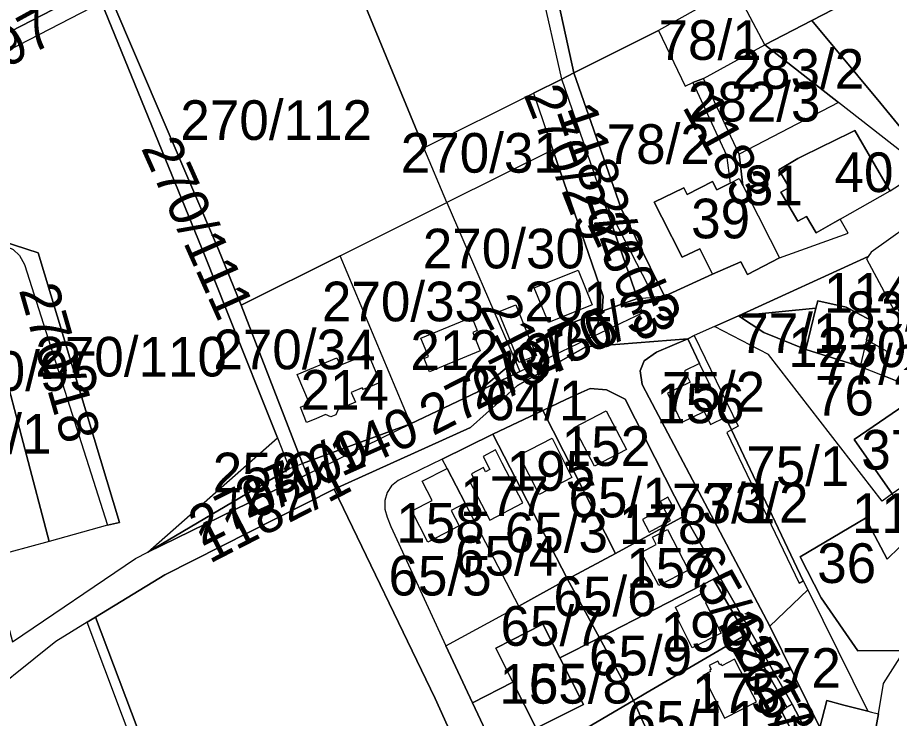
# Model space of a CAD drawing. Extents: x -623250 to -619626, y -1079612 to -1075424.
# Drawn here: x -621589.3 to -621368.8, y -1077090.4 to -1076913.6 of the extents above; entities that cross this region are included whole.
import ezdxf

# ---------------------------------------------------------------- set-up
doc = ezdxf.new("R2010")
doc.units = 0
doc.layers.add('Parcela nároku', color=7, linetype='Continuous')
doc.layers.add('Parcelní číslo', color=7, linetype='Continuous')

msp = doc.modelspace()

# ---------------------------------------------------------------- linework, layer by layer
at = {"layer": 'Parcela nároku'}
for points in [[(-621497.66, -1076887.41), (-621510.34, -1076889.38), (-621486.81, -1076946.46), (-621459.16, -1076932.7), (-621452.03, -1076929.15), (-621457.25, -1076905.73), (-621474.71, -1076864.09), (-621476.89, -1076864.41), (-621478.08, -1076856.31), (-621500.78, -1076808.08), (-621508.66, -1076809.23), (-621510.33, -1076797.86), (-621505.84, -1076797.19), (-621517.12, -1076774.19), (-621510.8, -1076809.47), (-621510.52, -1076812.14), (-621506.39, -1076828.53)], [(-621642.51, -1076849.57), (-621599.1, -1076820.91), (-621569.66, -1076906.06), (-621617.71, -1076930.85), (-621620.46, -1076931.89), (-621623.96, -1076932.1), (-621628.28, -1076930.73), (-621636.53, -1076902.24), (-621642.52, -1076868.77), (-621642.24, -1076853.29), (-621640.35, -1076852.51)], [(-621265.61, -1076833.49), (-621261.7, -1076848.72), (-621388.91, -1076914.43), (-621400.8, -1076920.49), (-621408.16, -1076906.52), (-621369.25, -1076886.43), (-621369.11, -1076886.7)], [(-621388.91, -1076914.43), (-621261.7, -1076848.72), (-621265.74, -1076862.26), (-621268.27, -1076865.58), (-621302.1, -1076905.64), (-621306.34, -1076911.31), (-621320.09, -1076923.81), (-621321.03, -1076924.46), (-621358.9, -1076950.67), (-621371.51, -1076935.3)], [(-621469.68, -1076868.53), (-621462.22, -1076885.24), (-621454.35, -1076902.86), (-621448.96, -1076927.61), (-621452.03, -1076929.15), (-621457.25, -1076905.73), (-621474.71, -1076864.09), (-621471.85, -1076863.67)], [(-621542.97, -1076896.85), (-621565.72, -1076908.58), (-621538.54, -1076972.15), (-621532.87, -1076986.13), (-621507.89, -1076973.7), (-621480.99, -1076960.31), (-621486.81, -1076946.46), (-621510.34, -1076889.38), (-621532.05, -1076893.05), (-621536.11, -1076893.99)], [(-621628.28, -1076930.73), (-621623.96, -1076932.1), (-621620.46, -1076931.89), (-621617.71, -1076930.85), (-621569.66, -1076906.06), (-621568.12, -1076909.82), (-621615.27, -1076934.15), (-621617.53, -1076935.48), (-621622.22, -1076939.58), (-621624.82, -1076942.64)], [(-621400.8, -1076920.49), (-621408.16, -1076906.52), (-621418.09, -1076911.65), (-621427.65, -1076916.93), (-621420.86, -1076930.98), (-621418.93, -1076930.03), (-621416.28, -1076928.99)], [(-621615.27, -1076934.15), (-621617.53, -1076935.48), (-621622.22, -1076939.58), (-621624.82, -1076942.64), (-621620.2, -1076960.77), (-621598.92, -1076968.16), (-621584.09, -1076972.99), (-621563.58, -1077040.98), (-621566.61, -1077041.67), (-621581.27, -1077045.75), (-621596.25, -1077049.81), (-621590.54, -1077071.06), (-621559.55, -1077050.01), (-621556.43, -1077048.44), (-621523.67, -1077019.62), (-621536.39, -1076987.8), (-621541.98, -1076973.85), (-621568.12, -1076909.82)], [(-621532.87, -1076986.13), (-621538.54, -1076972.15), (-621565.72, -1076908.58), (-621568.12, -1076909.82), (-621541.98, -1076973.85), (-621536.39, -1076987.8), (-621523.67, -1077019.62), (-621520.7, -1077027.31), (-621517.41, -1077026.07)], [(-621400.8, -1076920.49), (-621388.91, -1076914.43), (-621371.51, -1076935.3), (-621358.9, -1076950.67), (-621360.7, -1076951.91), (-621382.24, -1076935.03)], [(-621428.69, -1076960.22), (-621426.79, -1076963.96), (-621421.62, -1076974.1), (-621417.18, -1076971.93), (-621413.95, -1076978.36), (-621426.11, -1076983.89), (-621437.02, -1076961.76), (-621448.96, -1076927.61), (-621427.65, -1076916.93), (-621420.86, -1076930.98), (-621418.93, -1076930.03), (-621410.43, -1076948.36), (-621409.51, -1076955.38), (-621412.9, -1076957.1), (-621413.98, -1076954.99), (-621420.4, -1076958.27), (-621421.21, -1076956.59)], [(-621416.28, -1076928.99), (-621400.8, -1076920.49), (-621382.24, -1076935.03), (-621407.3, -1076948.06)], [(-621452.03, -1076929.15), (-621448.96, -1076927.61), (-621437.02, -1076961.76), (-621426.11, -1076983.89), (-621428.7, -1076984.16), (-621441.87, -1076958.52)], [(-621432.9, -1076984.48), (-621441.87, -1076958.52), (-621452.03, -1076929.15), (-621459.16, -1076932.7), (-621454.25, -1076947.01), (-621441.58, -1076983.87), (-621441.79, -1076987.68)], [(-621406.33, -1076956.01), (-621407.3, -1076948.06), (-621416.28, -1076928.99), (-621418.93, -1076930.03), (-621410.43, -1076948.36), (-621409.51, -1076955.38), (-621407.24, -1076954.23)], [(-621459.16, -1076932.7), (-621454.25, -1076947.01), (-621480.99, -1076960.31), (-621486.81, -1076946.46)], [(-621379.74, -1076967.98), (-621381.79, -1076964.51), (-621383.13, -1076965.27), (-621387.85, -1076967.95), (-621390.29, -1076963.84), (-621392.46, -1076965.01), (-621396.79, -1076957.69), (-621394.63, -1076956.52), (-621397.27, -1076952.05), (-621392.43, -1076949.18), (-621385.65, -1076945.85), (-621384.21, -1076945.15), (-621378.08, -1076942.14), (-621369.5, -1076956.9), (-621369.14, -1076957.33), (-621360.7, -1076951.91), (-621382.24, -1076935.03), (-621407.3, -1076948.06), (-621406.33, -1076956.01), (-621402.48, -1076963.6), (-621399.42, -1076969.63), (-621397.07, -1076974.26)], [(-621378.08, -1076942.14), (-621384.21, -1076945.15), (-621385.65, -1076945.85), (-621392.43, -1076949.18), (-621397.27, -1076952.05), (-621394.63, -1076956.52), (-621396.79, -1076957.69), (-621392.46, -1076965.01), (-621390.29, -1076963.84), (-621387.85, -1076967.95), (-621383.13, -1076965.27), (-621381.79, -1076964.51), (-621369.14, -1076957.33), (-621369.5, -1076956.9)], [(-621454.25, -1076947.01), (-621480.99, -1076960.31), (-621463.8, -1077000.14), (-621463.17, -1076999.62), (-621464.7, -1076995.86), (-621467.99, -1076987.82), (-621463.63, -1076986.06), (-621460.37, -1076994.09), (-621459.39, -1076996.45), (-621455.04, -1076992.81), (-621441.79, -1076987.68), (-621441.58, -1076983.87)], [(-621399.42, -1076969.63), (-621397.07, -1076974.26), (-621405.17, -1076978.41), (-621406.88, -1076975.24), (-621413.95, -1076978.36), (-621417.18, -1076971.93), (-621421.62, -1076974.1), (-621426.79, -1076963.96), (-621428.69, -1076960.22), (-621421.21, -1076956.59), (-621420.4, -1076958.27), (-621413.98, -1076954.99), (-621412.9, -1076957.1), (-621409.51, -1076955.38), (-621407.24, -1076954.23), (-621406.33, -1076956.01), (-621402.48, -1076963.6)], [(-621428.7, -1076984.16), (-621441.87, -1076958.52), (-621432.9, -1076984.48)], [(-621598.92, -1076968.16), (-621590.34, -1076972.12), (-621588.81, -1076973.64), (-621587.52, -1076975.91), (-621566.61, -1077041.67), (-621581.27, -1077045.75), (-621599.79, -1076975.67), (-621615.1, -1076979.74), (-621620.2, -1076960.77)], [(-621507.89, -1076973.7), (-621480.99, -1076960.31), (-621463.8, -1077000.14), (-621473.18, -1077007.98), (-621490.13, -1077016.07), (-621490.27, -1077015.75)], [(-621359.65, -1076964.2), (-621360.3, -1076963.02), (-621374.01, -1076972.77), (-621374.75, -1076973.9), (-621375.15, -1076974.51), (-621366.89, -1076989.84), (-621366.1, -1076989.42), (-621367.97, -1076985.39), (-621365.43, -1076983.95), (-621363.29, -1076987.92), (-621350.51, -1076980.67)], [(-621584.09, -1076972.99), (-621598.92, -1076968.16), (-621590.34, -1076972.12), (-621588.81, -1076973.64), (-621587.52, -1076975.91), (-621566.61, -1077041.67), (-621563.58, -1077040.98)], [(-621507.89, -1076973.7), (-621532.87, -1076986.13), (-621517.41, -1077026.07), (-621490.13, -1077016.07), (-621490.27, -1077015.75)], [(-621617.68, -1076980.42), (-621615.1, -1076979.74), (-621599.79, -1076975.67), (-621581.27, -1077045.75), (-621596.25, -1077049.81), (-621599.04, -1077050.56)], [(-621444.31, -1076986.08), (-621455.32, -1076990.52), (-621458.98, -1076981.75), (-621447.85, -1076977.35)], [(-621458.98, -1076981.75), (-621447.85, -1076977.35), (-621444.31, -1076986.08), (-621455.32, -1076990.52)], [(-621432.9, -1076984.48), (-621441.79, -1076987.68), (-621443.22, -1076991.6), (-621445.73, -1076994.82), (-621431.67, -1076988.07)], [(-621380.31, -1076986.66), (-621373.94, -1076990.04), (-621375.11, -1076994.94), (-621376.71, -1077001.63), (-621390.43, -1076997.35), (-621387.91, -1076986.95), (-621387.45, -1076985.07)], [(-621460.37, -1076994.09), (-621459.39, -1076996.45), (-621458.42, -1076998.81), (-621462.78, -1077000.59), (-621463.17, -1076999.62), (-621464.7, -1076995.86), (-621467.99, -1076987.82), (-621463.63, -1076986.06)], [(-621462.78, -1077000.59), (-621463.17, -1076999.62), (-621463.8, -1077000.14), (-621462.61, -1077002.91), (-621445.73, -1076994.82), (-621443.22, -1076991.6), (-621441.79, -1076987.68), (-621455.04, -1076992.81), (-621459.39, -1076996.45), (-621458.42, -1076998.81)], [(-621407.45, -1076988.85), (-621387.91, -1076986.95), (-621390.43, -1076997.35), (-621401, -1076993.07)], [(-621473.33, -1076992.53), (-621474.46, -1076993.04), (-621472.56, -1076997.65), (-621485.36, -1077002.94), (-621486.73, -1076999.6), (-621485.6, -1076999.12), (-621487.52, -1076994.5), (-621474.7, -1076989.2)], [(-621486.73, -1076999.6), (-621485.6, -1076999.12), (-621487.52, -1076994.5), (-621474.7, -1076989.2), (-621473.33, -1076992.53), (-621474.46, -1076993.04), (-621472.56, -1076997.65), (-621485.36, -1077002.94)], [(-621413.47, -1076991.52), (-621407.45, -1076988.85), (-621401, -1076993.07), (-621390.43, -1076997.35), (-621376.71, -1077001.63), (-621371.16, -1077003.85), (-621360.7, -1077008.03), (-621378.27, -1077020), (-621368.71, -1077033.73), (-621371.16, -1077035.61), (-621399.89, -1076998.58)], [(-621399.89, -1076998.58), (-621413.47, -1076991.52), (-621418.63, -1076993.81), (-621407.49, -1077016.65), (-621409.18, -1077017.58), (-621391.08, -1077055.64), (-621389.91, -1077057.9), (-621374.82, -1077088.56), (-621373.89, -1077088.8), (-621372.14, -1077089.23), (-621370.85, -1077081.53), (-621365.54, -1077073.2), (-621377.33, -1077073.32), (-621386.59, -1077059.95), (-621391.92, -1077049.63), (-621375.37, -1077039.83), (-621369.9, -1077050.16), (-621363.69, -1077044.16), (-621362.12, -1077042.64), (-621368.71, -1077033.73), (-621371.16, -1077035.61)], [(-621418.63, -1076993.81), (-621407.49, -1077016.65), (-621409.18, -1077017.58), (-621410.68, -1077014.4), (-621417.27, -1077000.87), (-621420.21, -1076994.61)], [(-621410.68, -1077014.4), (-621409.18, -1077017.58), (-621410.39, -1077018.26), (-621392.17, -1077056.23), (-621391.08, -1077055.64), (-621389.91, -1077057.9), (-621399.54, -1077067.08), (-621429.97, -1077009.54), (-621431.71, -1077006.2), (-621432.27, -1077002.68), (-621431.26, -1077000.22), (-621428.11, -1076997.98), (-621420.21, -1076994.61), (-621417.27, -1077000.87), (-621421.01, -1077002.68), (-621419.6, -1077005.58), (-621425.35, -1077008.37), (-621421.77, -1077015.74), (-621416.09, -1077012.97), (-621414.52, -1077016.24)], [(-621375.11, -1076994.94), (-621376.71, -1077001.63), (-621371.16, -1077003.85), (-621369.93, -1076997.81)], [(-621502.13, -1077007.46), (-621502.33, -1077007), (-621505.09, -1077008.16), (-621504.06, -1077010.64), (-621508.43, -1077012.46), (-621509, -1077013.82), (-621510.21, -1077014.31), (-621511.58, -1077013.76), (-621514.07, -1077014.79), (-621516.41, -1077015.76), (-621517.94, -1077011.9), (-621515.67, -1077010.97), (-621518.71, -1077003.65), (-621508.7, -1076999.48), (-621507.93, -1077001.32), (-621500.87, -1076998.4), (-621497.84, -1077005.66)], [(-621507.93, -1077001.32), (-621500.87, -1076998.4), (-621497.84, -1077005.66), (-621502.13, -1077007.46), (-621502.33, -1077007), (-621505.09, -1077008.16), (-621504.06, -1077010.64), (-621508.43, -1077012.46), (-621509, -1077013.82), (-621510.21, -1077014.31), (-621511.58, -1077013.76), (-621514.07, -1077014.79), (-621516.41, -1077015.76), (-621517.94, -1077011.9), (-621515.67, -1077010.97), (-621518.71, -1077003.65), (-621508.7, -1076999.48)], [(-621463.8, -1077000.14), (-621462.61, -1077002.91), (-621473.18, -1077007.98)], [(-621419.6, -1077005.58), (-621425.35, -1077008.37), (-621421.77, -1077015.74), (-621416.09, -1077012.97), (-621414.52, -1077016.24), (-621410.68, -1077014.4), (-621417.27, -1077000.87), (-621421.01, -1077002.68)], [(-621444.82, -1077007.21), (-621440.72, -1077007.52), (-621436.04, -1077009.88), (-621421.02, -1077039.31), (-621438.48, -1077048.76), (-621456.75, -1077012.69), (-621451, -1077009.98), (-621447.15, -1077008.19)], [(-621378.27, -1077020), (-621360.7, -1077008.03), (-621356.16, -1077015.71), (-621351.18, -1077024.13), (-621350.29, -1077025.63), (-621360.47, -1077033.73), (-621363.22, -1077029.96), (-621368.71, -1077033.73)], [(-621469.38, -1077018.71), (-621456.75, -1077012.69), (-621438.48, -1077048.76), (-621450.53, -1077055.28)], [(-621440.83, -1077012.83), (-621435.71, -1077022.59), (-621443.72, -1077026.79), (-621448.84, -1077017.03)], [(-621443.72, -1077026.79), (-621448.84, -1077017.03), (-621440.83, -1077012.83), (-621435.71, -1077022.59)], [(-621517.41, -1077026.07), (-621516.33, -1077028.86), (-621490.13, -1077016.07)], [(-621482.14, -1077025.01), (-621469.38, -1077018.71), (-621450.53, -1077055.28), (-621462.82, -1077062.01), (-621476.35, -1077036.1), (-621480.94, -1077027.3)], [(-621391.08, -1077055.64), (-621409.18, -1077017.58), (-621410.39, -1077018.26), (-621392.17, -1077056.23)], [(-621556.43, -1077048.44), (-621523.67, -1077019.62), (-621520.7, -1077027.31)], [(-621462.75, -1077023.97), (-621454.45, -1077019.71), (-621449.47, -1077029.61), (-621457.73, -1077033.89)], [(-621449.47, -1077029.61), (-621457.73, -1077033.89), (-621462.75, -1077023.97), (-621454.45, -1077019.71)], [(-621471.77, -1077027.13), (-621474.78, -1077028.71), (-621474.23, -1077029.77), (-621475.34, -1077030.35), (-621470.15, -1077040.33), (-621461.81, -1077035.99), (-621467.02, -1077026), (-621468.76, -1077022.67), (-621471.86, -1077024.29), (-621470.13, -1077027.62), (-621471.22, -1077028.2)], [(-621470.15, -1077040.33), (-621461.81, -1077035.99), (-621467.02, -1077026), (-621468.76, -1077022.67), (-621471.86, -1077024.29), (-621470.13, -1077027.62), (-621471.22, -1077028.2), (-621471.77, -1077027.13), (-621474.78, -1077028.71), (-621474.23, -1077029.77), (-621475.34, -1077030.35)], [(-621476.68, -1077036.28), (-621479.87, -1077037.94), (-621477.85, -1077041.82), (-621485.8, -1077045.9), (-621489.84, -1077038.05), (-621484.71, -1077035.41), (-621487.2, -1077030.57), (-621480.94, -1077027.3), (-621482.14, -1077025.01), (-621493.29, -1077030.35), (-621494.98, -1077031.74), (-621496.06, -1077033.42), (-621496.65, -1077035.41), (-621496.63, -1077037.56), (-621496.06, -1077039.6), (-621495.09, -1077041.96), (-621481.23, -1077072.02), (-621462.82, -1077062.01), (-621476.35, -1077036.1)], [(-621517.41, -1077026.07), (-621516.33, -1077028.86), (-621556.43, -1077048.44), (-621520.7, -1077027.31)], [(-621479.87, -1077037.94), (-621477.85, -1077041.82), (-621485.8, -1077045.9), (-621489.84, -1077038.05), (-621484.71, -1077035.41), (-621487.2, -1077030.57), (-621480.94, -1077027.3), (-621476.35, -1077036.1), (-621476.68, -1077036.28)], [(-621552.14, -1077054.14), (-621509.39, -1077032.53), (-621483.91, -1077085.32), (-621476.57, -1077101.71), (-621468.03, -1077126.7), (-621471.34, -1077128.84), (-621490.6, -1077164.95), (-621487.16, -1077167.11), (-621519.83, -1077191.99), (-621521.13, -1077193.21), (-621569.59, -1077064.81)], [(-621425.23, -1077034.59), (-621427.18, -1077035.64), (-621426.28, -1077037.3), (-621431.65, -1077040.21), (-621429.93, -1077043.4), (-621424.56, -1077040.49), (-621426.19, -1077037.48), (-621424.24, -1077036.42)], [(-621431.65, -1077040.21), (-621429.93, -1077043.4), (-621424.56, -1077040.49), (-621426.19, -1077037.48), (-621424.24, -1077036.42), (-621425.23, -1077034.59), (-621427.18, -1077035.64), (-621426.28, -1077037.3)], [(-621421.02, -1077039.31), (-621412.32, -1077054.52), (-621413.72, -1077055.24), (-621442.52, -1077070.01), (-621450.53, -1077055.28), (-621438.48, -1077048.76)], [(-621362.28, -1077058.96), (-621363.76, -1077052.36), (-621363.69, -1077044.16), (-621369.9, -1077050.16), (-621375.37, -1077039.83), (-621391.92, -1077049.63), (-621386.59, -1077059.95), (-621377.33, -1077073.32), (-621365.54, -1077073.2), (-621364.82, -1077065.54)], [(-621429.15, -1077044.66), (-621425.32, -1077042.69), (-621420.04, -1077052.94), (-621427.53, -1077056.8), (-621431.98, -1077048.49), (-621428.21, -1077046.49)], [(-621427.53, -1077056.8), (-621431.98, -1077048.49), (-621428.21, -1077046.49), (-621429.15, -1077044.66), (-621425.32, -1077042.69), (-621420.04, -1077052.94)], [(-621462.82, -1077062.01), (-621450.53, -1077055.28), (-621442.52, -1077070.01), (-621452.46, -1077075.11), (-621456.74, -1077066.63), (-621468.66, -1077072.65), (-621464.33, -1077081.2), (-621474.53, -1077086.43), (-621481.23, -1077072.02)], [(-621413.72, -1077055.24), (-621405.61, -1077069.31), (-621430.77, -1077083.96), (-621433.93, -1077085.81), (-621435.46, -1077082.99), (-621442.52, -1077070.01)], [(-621412.32, -1077054.52), (-621404.33, -1077068.49), (-621405.61, -1077069.31), (-621413.72, -1077055.24)], [(-621389.91, -1077057.9), (-621374.82, -1077088.56), (-621380.86, -1077086.97), (-621385.12, -1077085.85), (-621386.89, -1077092.62), (-621399.54, -1077067.08)], [(-621422.93, -1077064.97), (-621422.22, -1077064.6), (-621423.33, -1077062.27), (-621416.44, -1077058.68), (-621415.31, -1077060.94), (-621415.76, -1077061.2), (-621411.81, -1077068.87), (-621419.08, -1077072.58)], [(-621411.81, -1077068.87), (-621419.08, -1077072.58), (-621422.93, -1077064.97), (-621422.22, -1077064.6), (-621423.33, -1077062.27), (-621416.44, -1077058.68), (-621415.31, -1077060.94), (-621415.76, -1077061.2)], [(-621571.7, -1077066.1), (-621569.59, -1077064.81), (-621521.13, -1077193.21), (-621523.17, -1077195.12)], [(-621523.17, -1077195.12), (-621571.7, -1077066.1), (-621579.59, -1077070.93), (-621623.27, -1077105.92), (-621571.51, -1077228.57), (-621549.32, -1077220.52), (-621537.72, -1077208.73)], [(-621468.66, -1077072.65), (-621456.74, -1077066.63), (-621452.46, -1077075.11), (-621446.52, -1077086.85), (-621458.44, -1077092.81), (-621464.33, -1077081.2)], [(-621423.19, -1077102.63), (-621425.84, -1077104.04), (-621427.19, -1077100.87), (-621433.93, -1077085.81), (-621430.77, -1077083.96), (-621405.61, -1077069.31), (-621395.26, -1077087.55), (-621396.48, -1077088.72), (-621392.58, -1077096.32), (-621419.31, -1077101.34), (-621420.72, -1077101.24), (-621421.54, -1077101.66)], [(-621404.33, -1077068.49), (-621393.93, -1077086.79), (-621395.26, -1077087.55), (-621405.61, -1077069.31)], [(-621442.52, -1077070.01), (-621435.46, -1077082.99), (-621433.93, -1077085.81), (-621456.15, -1077098.84), (-621469.13, -1077097.83), (-621474.53, -1077086.43), (-621464.33, -1077081.2), (-621458.44, -1077092.81), (-621446.52, -1077086.85), (-621452.46, -1077075.11)], [(-621412.65, -1077075.89), (-621414.79, -1077077.03), (-621414.31, -1077077.96), (-621414.7, -1077078.16), (-621414.5, -1077078.56), (-621416.45, -1077079.56), (-621411.82, -1077088.54), (-621410.93, -1077090.29), (-621402.91, -1077086.19), (-621403.8, -1077084.44), (-621408.4, -1077075.44), (-621411.6, -1077077.08), (-621411.81, -1077076.67), (-621412.16, -1077076.85)], [(-621414.79, -1077077.03), (-621414.31, -1077077.96), (-621414.7, -1077078.16), (-621414.5, -1077078.56), (-621416.45, -1077079.56), (-621411.82, -1077088.54), (-621410.93, -1077090.29), (-621402.91, -1077086.19), (-621403.8, -1077084.44), (-621408.4, -1077075.44), (-621411.6, -1077077.08), (-621411.81, -1077076.67), (-621412.16, -1077076.85), (-621412.65, -1077075.89)], [(-621433.93, -1077085.81), (-621427.19, -1077100.87), (-621456.15, -1077098.84)], [(-621393.93, -1077086.79), (-621389.23, -1077095.72), (-621392.58, -1077096.32), (-621396.48, -1077088.72), (-621395.26, -1077087.55)], [(-621374.82, -1077088.56), (-621373.89, -1077088.8), (-621372.14, -1077089.23), (-621374.04, -1077099.65), (-621378.21, -1077107.34), (-621383.67, -1077097.7), (-621386.89, -1077092.62), (-621385.12, -1077085.85), (-621380.86, -1077086.97)]]:
    msp.add_lwpolyline(points, close=True, dxfattribs=at)
for points in [[(-621418.09, -1076911.65), (-621427.65, -1076916.93), (-621448.96, -1076927.61), (-621454.35, -1076902.86)], [(-621432.3, -1077203.73), (-621404.2, -1077162.3), (-621400.21, -1077156.98), (-621391.61, -1077145.5), (-621390.49, -1077143.5), (-621383.83, -1077133.32), (-621376.62, -1077119.92), (-621377.43, -1077118.16), (-621374.04, -1077099.65), (-621372.14, -1077089.23), (-621370.85, -1077081.53), (-621365.54, -1077073.2), (-621364.82, -1077065.54), (-621362.74, -1077065.56), (-621350.29, -1077025.63), (-621323.26, -1076972.15), (-621322.86, -1076971.35), (-621322.12, -1076969.47), (-621319.23, -1076962.06), (-621309.08, -1076943.03), (-621308.57, -1076943.53), (-621302.09, -1076930.63), (-621298.1, -1076925.1), (-621290.94, -1076911.65)], [(-621590.54, -1077071.06), (-621559.55, -1077050.01), (-621556.43, -1077048.44), (-621516.33, -1077028.86), (-621490.13, -1077016.07), (-621473.18, -1077007.98), (-621462.61, -1077002.91), (-621445.73, -1076994.82), (-621431.67, -1076988.07), (-621432.9, -1076984.48), (-621428.7, -1076984.16), (-621426.11, -1076983.89), (-621413.95, -1076978.36), (-621406.88, -1076975.24), (-621405.17, -1076978.41), (-621397.07, -1076974.26), (-621379.74, -1076967.98), (-621381.79, -1076964.51), (-621369.14, -1076957.33), (-621360.7, -1076951.91)], [(-621360.3, -1076963.02), (-621374.01, -1076972.77), (-621374.75, -1076973.9), (-621407.45, -1076988.85), (-621413.47, -1076991.52), (-621418.63, -1076993.81), (-621420.21, -1076994.61), (-621445.97, -1076996.63), (-621463.17, -1077006.38), (-621475, -1077017.01), (-621509.39, -1077032.53), (-621552.14, -1077054.14), (-621569.59, -1077064.81), (-621571.7, -1077066.1), (-621579.59, -1077070.93), (-621623.27, -1077105.92)], [(-621360.7, -1077008.03), (-621371.16, -1077003.85), (-621369.93, -1076997.81), (-621375.11, -1076994.94), (-621373.94, -1076990.04), (-621380.31, -1076986.66), (-621387.45, -1076985.07), (-621387.91, -1076986.95), (-621407.45, -1076988.85), (-621374.75, -1076973.9), (-621375.15, -1076974.51), (-621366.89, -1076989.84)], [(-621476.57, -1077101.71), (-621483.91, -1077085.32), (-621509.39, -1077032.53), (-621475, -1077017.01), (-621463.17, -1077006.38), (-621445.97, -1076996.63), (-621420.21, -1076994.61), (-621428.11, -1076997.98), (-621431.26, -1077000.22), (-621432.27, -1077002.68), (-621431.71, -1077006.2), (-621429.97, -1077009.54), (-621399.54, -1077067.08), (-621386.89, -1077092.62)], [(-621389.23, -1077095.72), (-621393.93, -1077086.79), (-621404.33, -1077068.49), (-621412.32, -1077054.52), (-621421.02, -1077039.31), (-621436.04, -1077009.88), (-621440.72, -1077007.52), (-621444.82, -1077007.21), (-621447.15, -1077008.19), (-621451, -1077009.98), (-621456.75, -1077012.69), (-621469.38, -1077018.71), (-621482.14, -1077025.01), (-621493.29, -1077030.35), (-621494.98, -1077031.74), (-621496.06, -1077033.42), (-621496.65, -1077035.41), (-621496.63, -1077037.56), (-621496.06, -1077039.6), (-621495.09, -1077041.96), (-621481.23, -1077072.02), (-621474.53, -1077086.43), (-621469.13, -1077097.83)]]:
    msp.add_lwpolyline(points, dxfattribs=at)

# ---------------------------------------------------------------- texts
at = {"layer": 'Parcelní číslo'}
for s, rotation, p in [('270/97', 28.6818, (-621614.98, -1076939.02)), ('270/29', 291.4806, (-621461.73, -1076932.98)), ('1183', 298.8268, (-621421.76, -1076936.11)), ('1182/2', 288.867, (-621453.45, -1076937.15)), ('270/111', 294.0953, (-621558.21, -1076946.53)), ('260/3', 294.7487, (-621445.72, -1076965.55)), ('270/18', 285.9316, (-621588.98, -1076982.29)), ('270/35', 23.1986, (-621458.61, -1077004.24)), ('213', 297, (-621473, -1076986.6)), ('270/36', 25.9672, (-621473.55, -1077012.73)), ('270/37', 26.9718, (-621484.53, -1077019.23)), ('270/140', 23.9795, (-621531.35, -1077040.09)), ('270/109', 26.565, (-621542.78, -1077047.1)), ('1182/1', 27.2025, (-621540.83, -1077051.43)), ('65/12', 299.2753, (-621421.97, -1077050.15)), ('65/13', 299.237, (-621412.25, -1077067.1)), ('65/16', 298.2288, (-621407, -1077078.61))]:
    msp.add_text(s, height=10, rotation=rotation, dxfattribs=at).set_placement(p)
for s, p in [('78/1', (-621427.61, -1076924.31)), ('283/2', (-621409.2, -1076931.61)), ('282/3', (-621420.22, -1076939.86)), ('270/112', (-621548.21, -1076944.5)), ('78/2', (-621440.69, -1076950.55)), ('270/31', (-621492.62, -1076952.76)), ('40', (-621383.22, -1076957.65)), ('81', (-621406.08, -1076960.97)), ('39', (-621419.38, -1076969.31)), ('270/30', (-621487.06, -1076976.89)), ('1141', (-621385.91, -1076988.04)), ('270/33', (-621512.5, -1076990.23)), ('201', (-621461.46, -1076990.22)), ('83/2', (-621380.34, -1076992.69)), ('77/1', (-621407.24, -1076998.22)), ('270/34', (-621539.88, -1077002.32)), ('1230', (-621394.88, -1077001.79)), ('270/110', (-621584.78, -1077004.15)), ('212', (-621490.19, -1077002.47)), ('77/2', (-621387.06, -1077006.18)), ('270/95', (-621609.66, -1077007.77)), ('214', (-621517.89, -1077012.5)), ('75/2', (-621426.75, -1077012.99)), ('64/1', (-621471.33, -1077015.17)), ('76', (-621388.16, -1077013.98)), ('156', (-621428.2, -1077015.93)), ('150/1', (-621614.16, -1077023.59)), ('152', (-621452.02, -1077026.7)), ('37', (-621376.47, -1077027.62)), ('195', (-621465.91, -1077032.97)), ('75/1', (-621405.49, -1077031.73)), ('259', (-621540.04, -1077033.35)), ('177', (-621477.64, -1077039.35)), ('65/1', (-621450.32, -1077039.67)), ('73/1', (-621424.18, -1077041.13)), ('73/2', (-621415.81, -1077041.02)), ('1184/12', (-621378.83, -1077043.62)), ('158', (-621493.76, -1077046.06)), ('178', (-621437.61, -1077046.37)), ('65/3', (-621466.38, -1077048.49)), ('65/4', (-621478.94, -1077054.33)), ('157', (-621435.77, -1077057.4)), ('36', (-621387.58, -1077056.21)), ('65/5', (-621495.71, -1077059.36)), ('65/6', (-621454.11, -1077064.58)), ('65/7', (-621467.46, -1077072.04)), ('196', (-621427.07, -1077073.51)), ('65/9', (-621445.15, -1077079.49)), ('72', (-621396.49, -1077082.63)), ('65/8', (-621460.33, -1077086.58)), ('155', (-621467.72, -1077086.63)), ('175', (-621419.19, -1077088.96)), ('65/11', (-621435.67, -1077095.95))]:
    msp.add_text(s, height=10, dxfattribs=at).set_placement(p)

doc.saveas('drawing.dxf')
